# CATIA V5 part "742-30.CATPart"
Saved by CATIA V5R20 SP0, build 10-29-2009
Part number: 742-30
Bounding box of the stored display mesh (mm): x -28 to 28.5, y -28 to 28, z -30 to 63
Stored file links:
  C:\Users\Utente\Desktop\IO LAVORO\3D X SITO CF\X SITO\742\742-30.CATPart
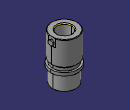
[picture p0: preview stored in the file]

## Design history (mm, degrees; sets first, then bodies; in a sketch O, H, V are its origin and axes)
Set1
  DatumSurface1 to DatumSurface38 "742-30"
Body1 (main body)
